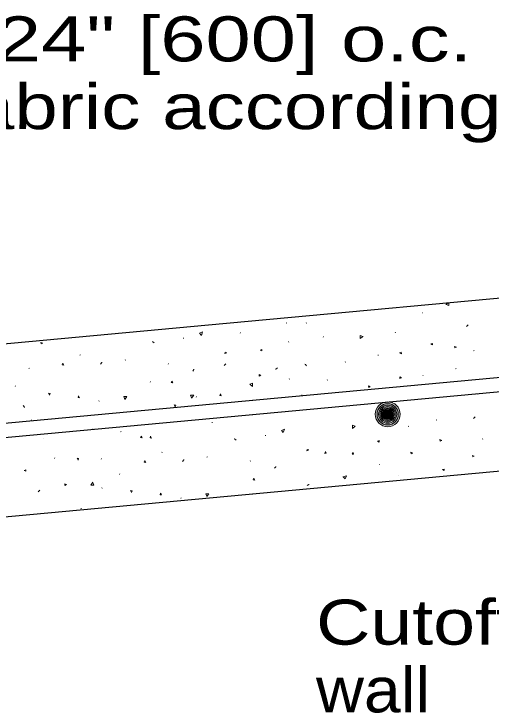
# Model space of a CAD drawing. Extents: x 1083.1 to 1117.1, y 697.4 to 741.4.
# Drawn here: x 1106.825 to 1108.478, y 723.378 to 725.801 of the extents above; entities that cross this region are included whole.
import ezdxf

# ---------------------------------------------------------------- set-up
doc = ezdxf.new("R2010")
doc.units = 0
doc.header["$LTSCALE"] = 0.062
doc.layers.add('1', color=7, linetype='Continuous', lineweight=13)

msp = doc.modelspace()

# ---------------------------------------------------------------- hatches: boundary and pattern name
at = {"layer": '1'}
h = msp.add_hatch(color=256, dxfattribs=at)
edge = h.paths.add_edge_path()
edge.add_ellipse((1108.12022, 724.41349), major_axis=(0.04324, 0), ratio=0.9998948, start_angle=0, end_angle=360)
h = msp.add_hatch(color=256, dxfattribs=at)
edge = h.paths.add_edge_path()
edge.add_ellipse((1108.12004, 724.41361), major_axis=(0.03676, 0), ratio=0.9998948, start_angle=0, end_angle=360)
h = msp.add_hatch(color=256, dxfattribs=at)
edge = h.paths.add_edge_path()
edge.add_ellipse((1108.11984, 724.41371), major_axis=(0.03124, 0), ratio=0.9998948, start_angle=0, end_angle=360)
h = msp.add_hatch(color=256, dxfattribs=at)
edge = h.paths.add_edge_path()
edge.add_ellipse((1108.11972, 724.4138), major_axis=(0.02656, 0), ratio=0.9998948, start_angle=0, end_angle=360)
h = msp.add_hatch(color=256, dxfattribs=at)
edge = h.paths.add_edge_path()
edge.add_ellipse((1108.11957, 724.41387), major_axis=(0.02257, 0), ratio=0.9998948, start_angle=0, end_angle=360)
h = msp.add_hatch(color=256, dxfattribs=at)
edge = h.paths.add_edge_path()
edge.add_ellipse((1108.11941, 724.41393), major_axis=(0.01919, 0), ratio=0.9998948, start_angle=0, end_angle=360)
h = msp.add_hatch(color=256, dxfattribs=at)
edge = h.paths.add_edge_path()
edge.add_ellipse((1108.11928, 724.41399), major_axis=(0.01631, 0), ratio=0.9998948, start_angle=0, end_angle=360)
h = msp.add_hatch(color=256, dxfattribs=at)
edge = h.paths.add_edge_path()
edge.add_ellipse((1108.11912, 724.41403), major_axis=(0.01386, 0), ratio=0.9998948, start_angle=0, end_angle=360)
h = msp.add_hatch(color=256, dxfattribs=at)
edge = h.paths.add_edge_path()
edge.add_ellipse((1108.11898, 724.41407), major_axis=(0.01178, 0), ratio=0.9998948, start_angle=0, end_angle=360)
h = msp.add_hatch(color=256, dxfattribs=at)
edge = h.paths.add_edge_path()
edge.add_ellipse((1108.11882, 724.4141), major_axis=(0.01002, 0), ratio=0.9998948, start_angle=0, end_angle=360)
h = msp.add_hatch(color=256, dxfattribs=at)
edge = h.paths.add_edge_path()
edge.add_ellipse((1108.11869, 724.41413), major_axis=(0.00851, 0), ratio=0.9998948, start_angle=0, end_angle=360)
h = msp.add_hatch(color=256, dxfattribs=at)
edge = h.paths.add_edge_path()
edge.add_ellipse((1108.11857, 724.4142), major_axis=(0.00724, 0), ratio=0.9998948, start_angle=0, end_angle=360)
h = msp.add_hatch(color=256, dxfattribs=at)
edge = h.paths.add_edge_path()
edge.add_ellipse((1108.11847, 724.41426), major_axis=(0.00615, 0), ratio=0.9998948, start_angle=0, end_angle=360)
h = msp.add_hatch(color=256, dxfattribs=at)
edge = h.paths.add_edge_path()
edge.add_ellipse((1108.11835, 724.41431), major_axis=(0.00523, 0), ratio=0.9998948, start_angle=0, end_angle=360)
h = msp.add_hatch(color=256, dxfattribs=at)
edge = h.paths.add_edge_path()
edge.add_ellipse((1108.11824, 724.41435), major_axis=(0.00444, 0), ratio=0.9998948, start_angle=0, end_angle=360)
h = msp.add_hatch(color=256, dxfattribs=at)
edge = h.paths.add_edge_path()
edge.add_ellipse((1108.11835, 724.41434), major_axis=(0.00378, 0), ratio=0.9998948, start_angle=0, end_angle=360)
h = msp.add_hatch(color=256, dxfattribs=at)
edge = h.paths.add_edge_path()
edge.add_ellipse((1108.11845, 724.41433), major_axis=(0.00321, 0), ratio=0.9998948, start_angle=0, end_angle=360)
h = msp.add_hatch(color=256, dxfattribs=at)
edge = h.paths.add_edge_path()
edge.add_ellipse((1108.11854, 724.41433), major_axis=(0.00273, 0), ratio=0.9998948, start_angle=0, end_angle=360)
h = msp.add_hatch(color=256, dxfattribs=at)
edge = h.paths.add_edge_path()
edge.add_ellipse((1108.11857, 724.41432), major_axis=(0.00232, 0), ratio=0.9998948, start_angle=0, end_angle=360)
h = msp.add_hatch(color=256, dxfattribs=at)
edge = h.paths.add_edge_path()
edge.add_ellipse((1108.11856, 724.41436), major_axis=(0.00197, 0), ratio=0.9998948, start_angle=0, end_angle=360)
h = msp.add_hatch(color=256, dxfattribs=at)
edge = h.paths.add_edge_path()
edge.add_ellipse((1108.11872, 724.41435), major_axis=(0.00168, 0), ratio=0.9998948, start_angle=0, end_angle=360)

# ---------------------------------------------------------------- linework, layer by layer
for p, q in [((1108.32183, 724.79408), (1108.32808, 724.79883)), ((1108.241, 724.7655), (1108.239, 724.76475)), ((1107.76858, 724.72933), (1107.77058, 724.73)), ((1107.83717, 724.7295), (1107.83917, 724.73017)), ((1107.60925, 724.69483), (1107.61008, 724.69675)), ((1108.14667, 724.69775), (1108.1455, 724.69617)), ((1107.41175, 724.67742), (1107.41375, 724.67675)), ((1107.898, 724.68267), (1107.89683, 724.68117)), ((1107.7775, 724.66392), (1107.77675, 724.66592)), ((1107.05375, 724.61867), (1107.05525, 724.61983)), ((1108.41917, 724.63408), (1108.41717, 724.63333)), ((1107.20992, 724.6015), (1107.21142, 724.60267)), ((1107.97225, 724.59442), (1107.97425, 724.59508)), ((1108.08575, 724.618), (1108.08775, 724.61867)), ((1106.8785, 724.57292), (1106.8765, 724.57217)), ((1107.36058, 724.58958), (1107.35975, 724.58758)), ((1108.35683, 724.57183), (1108.35492, 724.571)), ((1108.24333, 724.54825), (1108.24133, 724.54742)), ((1107.29817, 724.52725), (1107.2975, 724.52533)), ((1107.77867, 724.53492), (1107.7795, 724.53692)), ((1107.90992, 724.532), (1107.91192, 724.53283)), ((1106.8305, 724.51192), (1106.82933, 724.51042)), ((1107.45767, 724.47475), (1107.45683, 724.47283)), ((1107.82208, 724.48083), (1107.82283, 724.47883)), ((1108.43108, 724.48342), (1108.43225, 724.48492)), ((1107.12017, 724.46067), (1107.11942, 724.45875)), ((1106.88492, 724.39242), (1106.88567, 724.39442)), ((1107.44725, 724.39392), (1107.4465, 724.39192)), ((1107.5125, 724.385), (1107.5105, 724.38567)), ((1108.29025, 724.39383), (1108.28833, 724.393)), ((1107.0985, 724.36342), (1107.09767, 724.36142)), ((1107.19483, 724.35283), (1107.19642, 724.354)), ((1108.193, 724.372), (1108.191, 724.37133)), ((1106.92708, 724.32875), (1106.92717, 724.32867)), ((1107.69575, 724.34042), (1107.69775, 724.33967)), ((1108.44825, 724.32725), (1108.4495, 724.32883)), ((1107.33758, 724.28167), (1107.33908, 724.28283)), ((1106.96575, 724.26042), (1106.9665, 724.26242)), ((1107.12708, 724.25858), (1107.12792, 724.26058)), ((1107.49383, 724.2645), (1107.49533, 724.26567)), ((1107.64442, 724.25258), (1107.64375, 724.25058)), ((1108.08992, 724.23925), (1108.09192, 724.24008)), ((1107.19158, 724.20683), (1107.19075, 724.20483)), ((1108.15833, 724.20075), (1108.15817, 724.20075)), ((1107.13058, 724.15883), (1107.12908, 724.15767)), ((1107.40408, 724.12367), (1107.40333, 724.12175)), ((1107.0575, 724.08608), (1107.05833, 724.088))]:
    msp.add_line(p, q, dxfattribs=at)
at = {"layer": '1', "lineweight": 25}
for p, q in [((1110.5145, 724.72675), (1103.31092, 724.05875)), ((1110.51908, 724.67717), (1103.29317, 724.007)), ((1110.14883, 724.368), (1103.29017, 723.73208))]:
    msp.add_line(p, q, dxfattribs=at)
msp.add_lwpolyline([(1110.14883, 724.96767), (1107.49917, 724.722), (1103.29017, 724.33175)], dxfattribs=at)
at = {"layer": '1'}
for points in [[(1108.33158, 724.79917), (1108.33142, 724.79058), (1108.322, 724.794)], [(1108.3985, 724.7235), (1108.39792, 724.72208), (1108.393, 724.71792)], [(1107.4745, 724.68692), (1107.478, 724.69875), (1107.46783, 724.69483), (1107.47433, 724.68717)], [(1108.0345, 724.68342), (1108.02458, 724.676), (1108.02475, 724.68692), (1108.03425, 724.6835)], [(1107.3055, 724.66625), (1107.30608, 724.66483), (1107.31108, 724.66067)], [(1107.131, 724.59308), (1107.12958, 724.5925), (1107.12542, 724.5875)], [(1107.5535, 724.583), (1107.55475, 724.58358), (1107.559, 724.58858)], [(1107.73233, 724.569), (1107.73292, 724.57042), (1107.73792, 724.57458)], [(1107.83325, 724.58708), (1107.83467, 724.5865), (1107.83883, 724.5815)], [(1107.44992, 724.56892), (1107.4485, 724.56833), (1107.44442, 724.56342)], [(1107.64225, 724.51742), (1107.652, 724.51), (1107.65192, 724.52092), (1107.64242, 724.5175)], [(1107.20917, 724.46517), (1107.21658, 724.47492), (1107.20567, 724.47475), (1107.20908, 724.46533)], [(1107.44067, 724.46992), (1107.448, 724.47975), (1107.437, 724.47958), (1107.4405, 724.47008)], [(1106.86292, 724.43817), (1106.8615, 724.43875), (1106.85742, 724.44375)], [(1108.42267, 724.40458), (1108.42208, 724.40317), (1108.41708, 724.399)], [(1107.75842, 724.34992), (1107.762, 724.36175), (1107.75167, 724.35775), (1107.75817, 724.35017)], [(1108.00733, 724.37208), (1107.9975, 724.36458), (1107.99767, 724.37558), (1108.00717, 724.37225)], [(1107.58933, 724.32925), (1107.59, 724.32783), (1107.595, 724.32367)], [(1107.41483, 724.25608), (1107.41342, 724.2555), (1107.40933, 724.2505)], [(1107.73392, 724.23192), (1107.7325, 724.23133), (1107.72833, 724.22642)], [(1107.965, 724.1965), (1107.97675, 724.2), (1107.97275, 724.18983), (1107.96517, 724.19633)], [(1107.0985, 724.17783), (1107.09108, 724.16792), (1107.10208, 724.16817), (1107.09858, 724.17758)], [(1107.84692, 724.17192), (1107.84633, 724.1705), (1107.84142, 724.16642)], [(1106.90867, 724.14533), (1106.91008, 724.14592), (1106.91425, 724.15092)], [(1107.493, 724.12817), (1107.5005, 724.13792), (1107.4895, 724.13775), (1107.493, 724.12833)]]:
    msp.add_lwpolyline(points, dxfattribs=at)
for points in [[(1106.92508, 724.65958), (1106.9195, 724.65767), (1106.91875, 724.66283)], [(1108.26925, 724.65742), (1108.27483, 724.65942), (1108.27567, 724.65417)], [(1108.35833, 724.64558), (1108.35275, 724.64358), (1108.352, 724.64883)], [(1107.56267, 724.627), (1107.55708, 724.629), (1107.55625, 724.62367)], [(1107.67817, 724.63625), (1107.68367, 724.63825), (1107.68442, 724.633)], [(1108.16117, 724.62658), (1108.16683, 724.62858), (1108.1675, 724.62325)], [(1106.99433, 724.59042), (1106.99233, 724.58475), (1106.99767, 724.58408)], [(1107.68058, 724.54933), (1107.675, 724.55133), (1107.67433, 724.546)], [(1107.372, 724.52875), (1107.37008, 724.52317), (1107.37533, 724.52242)], [(1108.16792, 724.5395), (1108.16233, 724.53758), (1108.16158, 724.54292)], [(1108.05983, 724.50875), (1108.05425, 724.50675), (1108.05342, 724.512)], [(1106.94833, 724.48008), (1106.95033, 724.48567), (1106.94508, 724.48642)], [(1107.04933, 724.47742), (1107.04733, 724.47183), (1107.05258, 724.47108)], [(1107.54017, 724.48442), (1107.53833, 724.47883), (1107.54358, 724.47808)], [(1107.38383, 724.43967), (1107.38583, 724.44525), (1107.38058, 724.44608)], [(1107.266, 724.33833), (1107.264, 724.33275), (1107.26933, 724.332)], [(1107.2985, 724.3375), (1107.2965, 724.332), (1107.30183, 724.33125)], [(1108.08433, 724.32075), (1108.08992, 724.32267), (1108.09075, 724.31742)], [(1108.307, 724.32283), (1108.30142, 724.32083), (1108.30067, 724.32617)], [(1107.84658, 724.28992), (1107.84092, 724.292), (1107.84025, 724.28667)], [(1107.905, 724.28467), (1107.907, 724.27908), (1107.90175, 724.27825)], [(1108.00008, 724.28117), (1108.00208, 724.27558), (1107.99675, 724.27483)], [(1108.20692, 724.27867), (1108.20125, 724.27667), (1108.20058, 724.282)], [(1107.04708, 724.25475), (1107.04908, 724.26042), (1107.04383, 724.26117)], [(1108.42, 724.26792), (1108.41442, 724.266), (1108.41367, 724.27117)], [(1107.27825, 724.25342), (1107.27625, 724.24775), (1107.2815, 724.24708)], [(1106.86025, 724.21833), (1106.86583, 724.21633), (1106.86658, 724.22158)], [(1108.30967, 724.222), (1108.31525, 724.22392), (1108.316, 724.21867)], [(1107.65592, 724.19175), (1107.65392, 724.18608), (1107.65925, 724.18542)], [(1107.0075, 724.1705), (1107.00192, 724.1725), (1107.00125, 724.16725)], [(1107.23233, 724.14308), (1107.23425, 724.14867), (1107.22892, 724.14942)], [(1107.33317, 724.14042), (1107.33117, 724.13483), (1107.3365, 724.13408)]]:
    msp.add_lwpolyline(points, close=True, dxfattribs=at)
for centre, major_axis in [((1108.12022, 724.41349), (0.04324, 0)), ((1108.12004, 724.41361), (0.03676, 0)), ((1108.11984, 724.41371), (0.03124, 0)), ((1108.11972, 724.4138), (0.02656, 0)), ((1108.11957, 724.41387), (0.02257, 0)), ((1108.11941, 724.41393), (0.01919, 0)), ((1108.11928, 724.41399), (0.01631, 0)), ((1108.11912, 724.41403), (0.01386, 0)), ((1108.11898, 724.41407), (0.01178, 0)), ((1108.11882, 724.4141), (0.01002, 0)), ((1108.11869, 724.41413), (0.00851, 0)), ((1108.11857, 724.4142), (0.00724, 0)), ((1108.11847, 724.41426), (0.00615, 0)), ((1108.11835, 724.41431), (0.00523, 0)), ((1108.11824, 724.41435), (0.00444, 0)), ((1108.11835, 724.41434), (0.00378, 0)), ((1108.11845, 724.41433), (0.00321, 0)), ((1108.11854, 724.41433), (0.00273, 0)), ((1108.11857, 724.41432), (0.00232, 0)), ((1108.11856, 724.41436), (0.00197, 0)), ((1108.11872, 724.41435), (0.00168, 0))]:
    msp.add_ellipse(centre, major_axis=major_axis, ratio=0.999895, dxfattribs=at)

# ---------------------------------------------------------------- texts
for s, width, p in [('#3 [#10M] round bars, at 24" [600] o.c.', 1.35, (1103.61583, 725.63633)), ('in two directions, or wire fabric according ', 1.3, (1103.61583, 725.40167)), ('Cutoff', 1.25, (1107.87183, 723.61533)), ('wall', 1.1, (1107.87183, 723.38067))]:
    msp.add_text(s, height=0.156, dxfattribs=dict(at, width=width)).set_placement(p)

doc.saveas('drawing.dxf')
